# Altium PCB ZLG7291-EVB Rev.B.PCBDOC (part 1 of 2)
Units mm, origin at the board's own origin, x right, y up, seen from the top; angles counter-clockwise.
Board outline 90 x 60 mm, 2 copper layers (Top Layer, Bottom Layer); 77 components, 55 nets, 304 pads, 258 vias.
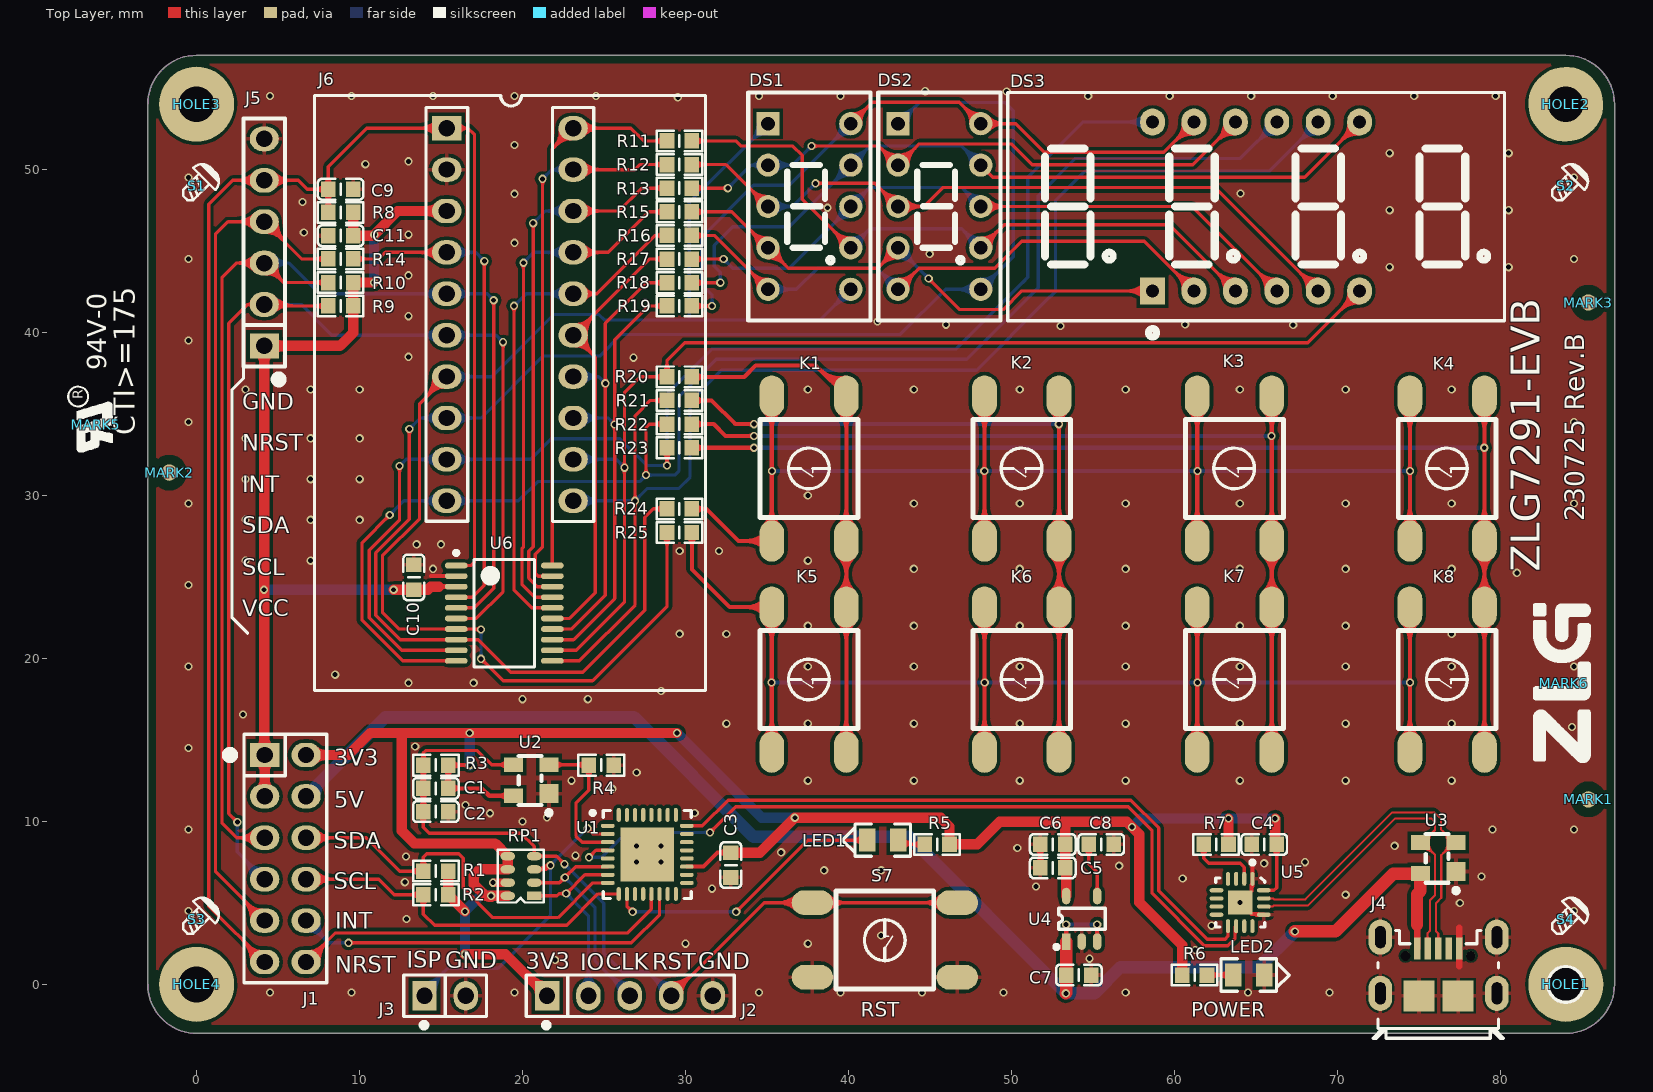
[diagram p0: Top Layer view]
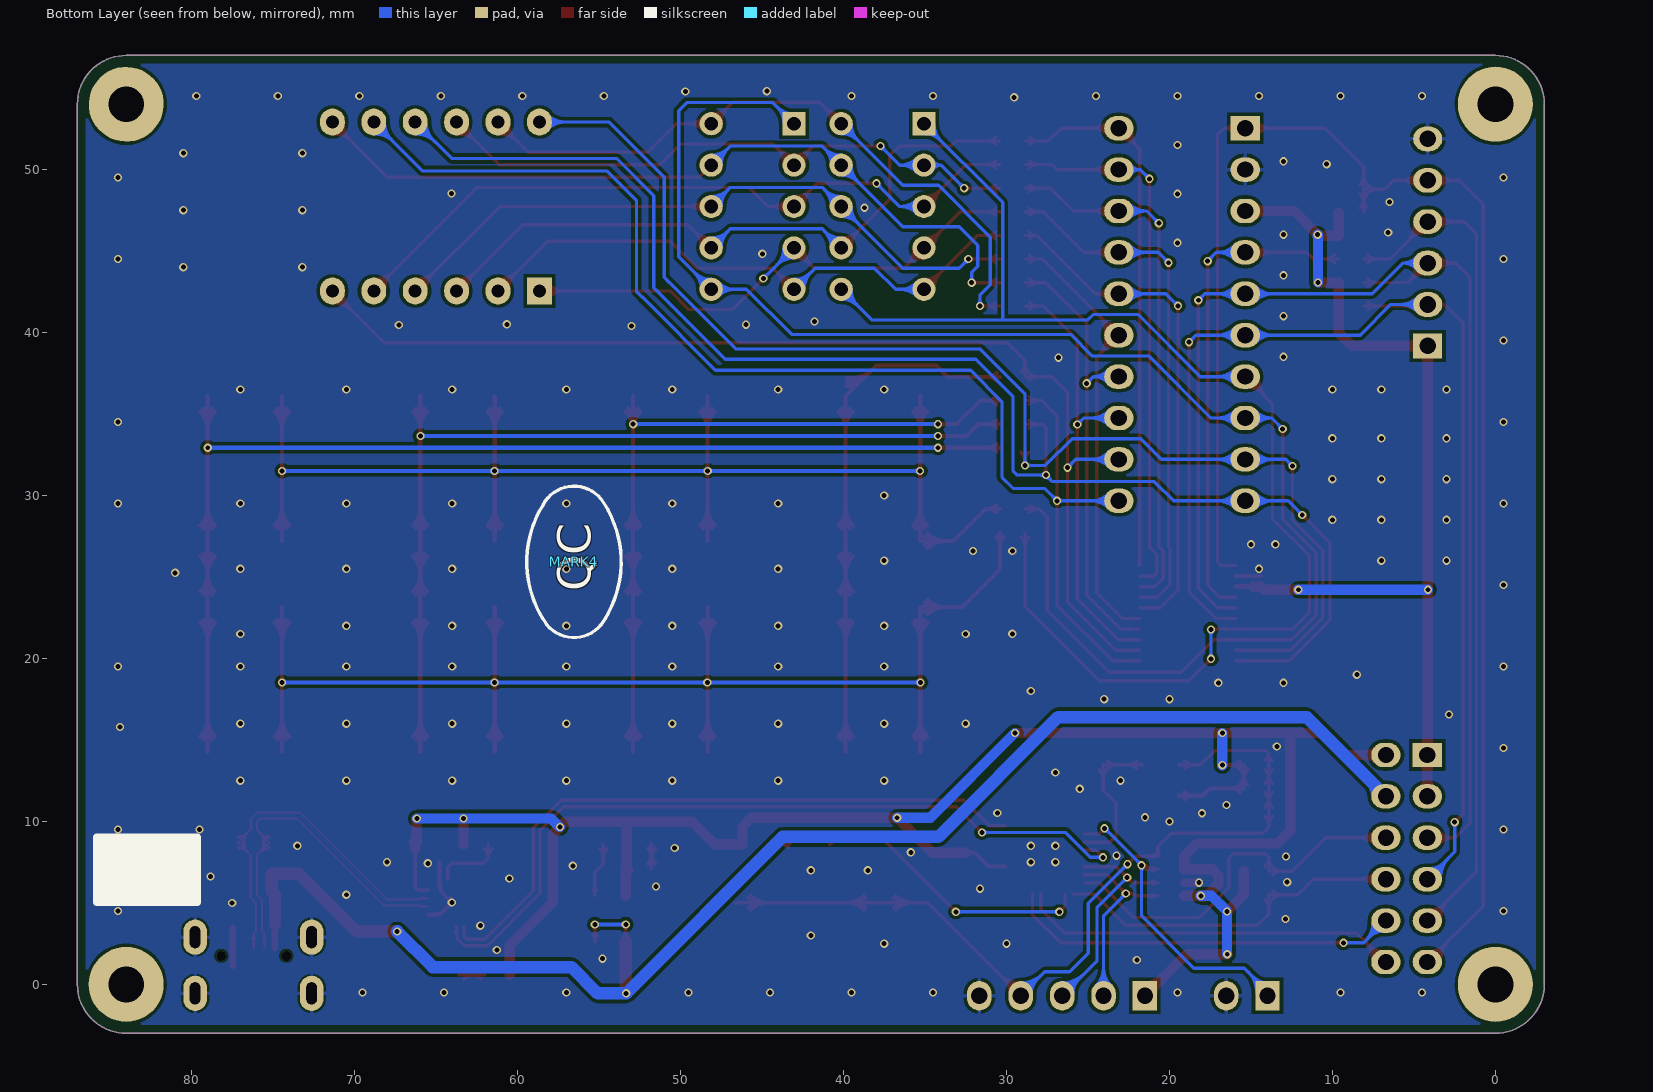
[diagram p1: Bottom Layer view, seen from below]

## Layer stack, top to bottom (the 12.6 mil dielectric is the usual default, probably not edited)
Top Layer: signal copper 0.0356
Dielectric: dielectric 0.32, FR-4, Dk 4.8
Bottom Layer: signal copper 0.0356

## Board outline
-3,0 -3,54 cw(c0,54) 0,57 84,57 cw(c84,54) 87,54 87,0 cw(c84,0) 84,-3 0,-3 cw(c0,0)

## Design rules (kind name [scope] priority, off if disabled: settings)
Clearance Clearance_2 [(OnLayer('Keep-Out Layer'))] p1: gap=0.508
Clearance Clearance_1 [(InComponent('J4'))] p2: gap=0.127
Clearance [All] p3: gap=0.203
ComponentClearance [All] p1 off: gap=0.254 collisioncheckmode=3 verticalgap=0.254 showdistances=FALSE
DiffPairsRouting [All] p1: maxlimit=0.254 minlimit=0.254 mostfreqgap=0.254 maxuncoupledlength=12.7
MinimumSolderMaskSliver [All] p1 off: minsoldermaskwidth=0.254
PolygonConnect PolygonConnect_1 [ISVIA] p1: connectstyle=Direct reliefconductorwidth=0.254 reliefentries=4 polygonreliefangle="90 Angle"
PolygonConnect [All] p2: connectstyle=Relief reliefconductorwidth=0.254 reliefentries=4 polygonreliefangle="90 Angle"
RoutingVias [All] p1: holewidth=0.711 width=1.27 viastyle="Through Hole" minholewidth=0.711 minwidth=1.27 maxholewidth=0.711 maxwidth=1.27
SilkToSilkClearance [All] p1 off: silktosilkclearance=0.254
SilkscreenOverComponentPads [All] p1 off: minsilkscreentomaskgap=0.254
SolderMaskExpansion [All] p1: expansion=0.102
Width [All] p1: maxlimit=2.54 minlimit=0.127 preferedwidth=0.203 minimp=50.000000 maximp=50.000000 favimp=50.000000
23 further rules are at their usual default settings.

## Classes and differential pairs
component class ZLG7291: C9 C10 C11 DS1 DS2 DS3 J5 J6 K1 K2 K3 K4 K5 K6 K7 K8 R8 R9 R10 R11 R12 R13 R14 R15 R16 R17 R18 R19 R20 R21 R22 R23 R24 R25 U6
component class POWER: C4 C5 C6 C7 C8 J4 LED1 LED2 R5 R6 R7 U3 U4 U5
component class LPC824: C1 C2 C3 HOLE1 HOLE2 HOLE3 HOLE4 J1 J2 J3 MARK1 MARK2 MARK3 MARK4 MARK5 MARK6 R1 R2 R3 R4 RP1 S1 S2 S3 S4 S7 U1 U2
differential pair USB: +USB_P -USB_N

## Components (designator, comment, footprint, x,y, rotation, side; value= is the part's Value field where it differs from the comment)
C1 "0.1uF,50V,0603" 0603C 14.675,12.025 r180 top
C2 "0.1uF,50V,0603" 0603C 14.675,10.6 r0 top
C3 "0.1uF,50V,0603" 0603C 32.775,7.325 r270 top
C4 "0.1uF,50V,0603" 0603C 65.5,8.588 r180 top
C5 "10uF,25V,0603" 0603C 52.525,7.15 r180 top
C6 "0.1uF,50V,0603" 0603C 52.525,8.588 r180 top
C7 "10uF,25V,0603" 0603C 54.125,0.575 r0 top
C8 "50V,MURATA,103" 0603C 55.5,8.588 r0 top
C9 "0.1uF,50V,0603" 0603C 8.838,48.785 r0 top
C10 "1uF,50V,0603" 0603C 13.325,24.975 r90 top
C11 "1uF,50V,0603" 0603C 8.838,45.935 r180 top
DS1 "LN3161AS2B,LN" LN3161 37.597,47.725 r0 top
DS2 "LN3161AS2B,LN" LN3161 45.572,47.725 r0 top (schematic designator DS3)
DS3 "LN3461AS2B,LN" LN3461-3000X1400X720 65,47.725 r0 top (schematic designator DS2)
HOLE1 "HOLE - 不上螺丝" HOLE-2.2 84,0 r90 top
HOLE2 "HOLE - 不上螺丝" HOLE-2.2 84,54 r107 top
HOLE3 "HOLE - 不上螺丝" HOLE-2.2 0,54 r330 top
HOLE4 "HOLE - 不上螺丝" HOLE-2.2 0,0 r30 top
J1 "HEADER 6X2" IDC-12-2.54 4.175,14.075 r270 top
J2 "SWD" SIP-5-2.54 21.5,-0.7 r0 top
J3 "ISP" SIP-2-2.54 15.25,-0.7 r0 top
J4 "ST-USB-002B-1,SMT" MICROUSB-ST-USB-002B-1 76.2,1.1 r0 top
J5 "CON6" SIP-6-2.54 4.15,45.525 r90 top
J6 "HEADER 10X2" TEST-TSSOP20 19.225,41.1 r0 top locked
K1 "TS0641-0501B,SMD" KEY-6S 37.575,31.65 r90 top
K2 "TS0641-0501B,SMD" KEY-6S 50.624,31.65 r90 top
K3 "TS0641-0501B,SMD" KEY-6S 63.674,31.65 r90 top
K4 "TS0641-0501B,SMD" KEY-6S 76.723,31.65 r90 top
K5 "TS0641-0501B,SMD" KEY-6S 37.575,18.7 r90 top
K6 "TS0641-0501B,SMD" KEY-6S 50.624,18.7 r90 top
K7 "TS0641-0501B,SMD" KEY-6S 63.674,18.7 r90 top
K8 "TS0641-0501B,SMD" KEY-6S 76.723,18.7 r90 top
LED1 "绿色,0805" LED-0805 42.1,8.85 r180 top
LED2 "红色,0805" LED-0805 64.55,0.575 r0 top
MARK1 "MARKER" MARKER-C-1.0M 85.392,11.351 r0 top
MARK2 "MARKER" MARKER-C-1.0M -1.675,31.4 r0 top
MARK3 "MARKER" MARKER-C-1.0M 85.392,41.831 r0 top
MARK4 "ZY QC" ZY_QC 56.531,25.923 r90 bottom
MARK5 "UR" ZY_UR-3X2 -6.175,34.338 r90 top
MARK6 "ZLGLOGO" ZLG0.5 83.868,18.463 r90 top
R1 "4.7KΩ,±5%,0603" 0603R 14.675,6.95 r0 top
R2 "4.7KΩ,±5%,0603" 0603R 14.675,5.5 r0 top
R3 "10KΩ,±5%,0603" 0603R 14.675,13.45 r0 top
R4 "100KΩ,±5%,0603" 0603R 24.825,13.45 r180 top
R5 "1.5KΩ,±5%,0603" 0603R 45.425,8.588 r180 top
R6 "1.5KΩ,±5%,0603" 0603R 61.225,0.575 r0 top
R7 "4.7KΩ,±5%,0603" 0603R 62.55,8.588 r0 top
R8 "4.7KΩ,±5%,0603" 0603R 8.838,47.36 r0 top
R9 "4.7KΩ,±5%,0603" 0603R 8.838,41.625 r0 top
R10 "4.7KΩ,±5%,0603" 0603R 8.838,43.06 r0 top
R11 "200Ω,±5%,0603" 0603R 29.625,51.75 r0 top
R12 "200Ω,±5%,0603" 0603R 29.625,50.3 r0 top
R13 "200Ω,±5%,0603" 0603R 29.625,48.85 r0 top
R14 "200Ω,±5%,0603" 0603R 8.838,44.51 r0 top
R15 "200Ω,±5%,0603" 0603R 29.625,47.4 r0 top
R16 "200Ω,±5%,0603" 0603R 29.625,45.95 r0 top
R17 "200Ω,±5%,0603" 0603R 29.625,44.5 r0 top
R18 "200Ω,±5%,0603" 0603R 29.625,43.05 r0 top
R19 "200Ω,±5%,0603" 0603R 29.625,41.625 r0 top
R20 "1KΩ,±5%,0603" 0603R 29.625,37.275 r180 top
R21 "1KΩ,±5%,0603" 0603R 29.625,35.825 r180 top
R22 "1KΩ,±5%,0603" 0603R 29.625,34.375 r180 top
R23 "1KΩ,±5%,0603" 0603R 29.625,32.925 r180 top
R24 "1KΩ,±5%,0603" 0603R 29.625,29.175 r180 top
R25 "1KΩ,±5%,0603" 0603R 29.625,27.725 r180 top
RP1 "RTA03-4D103JTP,SMD" 0603RA 19.9,6.65 r180 top
S1 "Value" Screw-Mark2 0,49 r0 top
S2 "Value" Screw-Mark2 84,49 r0 top
S3 "Value" Screw-Mark2 0,4 r0 top
S4 "Value" Screw-Mark2 84,4 r0 top
S7 "DTSM-62R-V-T/R,SMD" KEY-6S 42.225,2.725 r180 top
U1 "LPC824M201JHI33,HVQFN-33" QFN50P500X500X85-33N 27.65,7.975 r0 top
U2 "CAT811STBI-GT3,SOT143(4)" SOT-143 20.525,12.525 r180 top
U3 "PRTR5V0U2X,SOT143/SOT4" sot-143 76.175,7.75 r180 top
U4 "ZL6205A33TS5" SOT-23-5 54.3,4.025 r90 top
U5 "XR21V1410IL16TR-F,QFN-16" QFN50P300X300X80-17AN 64.025,5.025 r270 top
U6 "ZLG7291" TSOP65P640X120-20N 18.875,22.775 r0 top

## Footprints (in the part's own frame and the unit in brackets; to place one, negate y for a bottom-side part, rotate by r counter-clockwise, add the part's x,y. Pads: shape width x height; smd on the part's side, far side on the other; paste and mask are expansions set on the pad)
0603C [mm] "ZLGLIB"
  rect 0.9x0.95 smd: 1(-0.762,0) 2(0.762,0)
  Top Layer pour cut-out: -0.2,0.575 -0.2,-0.575 0.2,-0.575 0.2,0.575
  silkscreen extent -1.4,-0.64 1.4,0.64, body extent -0.79,-0.38 0.81,0.42, height 0.3
0603R [mm] "ZLGLIB"
  rect 0.9x0.95 smd: 1(-0.762,0) 2(0.762,0)
  Top Layer pour cut-out: -0.2,0.575 -0.2,-0.575 0.2,-0.575 0.2,0.575
  silkscreen extent -1.4,-0.64 1.4,0.64, body extent -0.8,-0.4 0.8,0.4, height 0.3
0603RA [mil] "ZLGLIB"
  rect 35x20 smd: 1(-32,48)
  oval 35x20 smd: 2(-32,16) 3(-32,-16) 4(-32,-48) 5(32,-48) 6(32,-16) 7(32,16) 8(32,48)
  Top Layer pour cut-out: -53.5,62 53.5,62 53.5,-62 -53.5,-62
  silkscreen extent -55,-64 56,64, body extent -33,-63 33,63, height 22
HOLE-2.2 [mm]
  round 4.6 hole 2.2: 1(0,0)
IDC-12-2.54 [mm]
  rect 1.5x1.8 hole 1: 1(0,0)
  oval 1.5x1.8 hole 1: 2(0,2.54) 3(2.54,0) 4(2.54,2.54) 5(5.08,0) 6(5.08,2.54) 7(7.62,0) 8(7.62,2.54) 9(10.16,0) 10(10.16,2.54) 11(12.7,0) 12(12.7,2.54)
  silkscreen extent -1.27,-2.38 13.97,3.81, body extent -1.27,-1.27 13.97,3.81, height 7.58
KEY-6S [mil] "ZLGLIB"
  oval 100x60 smd: 1(-175,90) 2(-175,-90) 3(175,-90) 4(175,90)
  silkscreen extent -118,-118 118,118, body extent -201,-122 201,122, height 268
LED-0805 [mm] "170907内距改0.9mm,ZLGLIB"
  rect 1.014x1.4 smd: 1(-0.957,0) 2(0.957,0)
  silkscreen extent -1.7,-0.99 2.49,0.99, body extent -1,-0.64 1,0.64, height 1.1
LN3161 [mil] "ZLGLIB"
  rect 56x56 hole 33: 1(-100,200)
  round 56 hole 33: 2(-100,100) 3(-100,0) 4(-100,-100) 5(-100,-200) 6(100,-200) 7(100,-100) 8(100,0) 9(100,100) 10(100,200)
  silkscreen extent -148,-276 148,276
LN3461-3000X1400X720 [mm] "ZLGLIB"
  rect 1.524x1.651 hole 0.8: 1(-6.35,-5.18)
  oval 1.524x1.651 hole 0.8: 2(-3.81,-5.18) 3(-1.27,-5.18) 4(1.27,-5.18) 5(3.81,-5.18) 6(6.35,-5.18) 7(6.35,5.18) 8(3.81,5.18) 9(1.27,5.18) 10(-1.27,5.18) 11(-3.81,5.18) 12(-6.35,5.18)
  silkscreen extent -15.24,-8 15.24,7
MARKER-C-1.0M [mm]
  round 1 smd paste-1.016 mask+0.5: 0(0,0)
  Top Layer pour cut-out: -1.1,0 -1.016,-0.421 -0.778,-0.778 -0.421,-1.016 0,-1.1 0,-1.1 0.421,-1.016 0.778,-0.778 1.016,-0.421 1.1,0 1.1,0 1.016,0.421 0.778,0.778 0.421,1.016 0,1.1 0,1.1 -0.421,1.016 -0.778,0.778 -1.016,0.421 -1.1,0
MICROUSB-ST-USB-002B-1 [mm] "ZLGLIB"
  oval 1.45x2.15 on Top Paste: 0(-3.575,-1.65) 0(-3.575,1.8) 0(3.575,-1.65) 0(3.575,1.8)
  round 0.55 hole 0.6 unplated: 0(-2.025,0.65) 0(1.975,0.65)
  rect 0.4x1.35 smd: 1(-1.325,1.115) 2(-0.675,1.115) 3(-0.025,1.115) 4(0.625,1.115) 5(1.275,1.115)
  oval 1.45x2.15 hole 0.65 slot 1.35 at 90 deg: 6(-3.575,1.8) 7(3.575,1.8) 8(-3.575,-1.65) 9(3.575,-1.65)
  rect 1.9x1.9 smd: 10(-1.2,-1.8) 11(1.2,-1.8)
  silkscreen extent -4.02,-4.4 3.98,2.2
QFN50P300X300X80-17AN [mm] "ZLGLIB"
  oval 0.85x0.25 smd: 1(-1.45,0.75) 2(-1.45,0.25) 3(-1.45,-0.25) 4(-1.45,-0.75) 9(1.45,-0.75) 10(1.45,-0.25) 11(1.45,0.25) 12(1.45,0.75)
  oval 0.25x0.85 smd: 5(-0.75,-1.45) 6(-0.25,-1.45) 7(0.25,-1.45) 8(0.75,-1.45) 13(0.75,1.45) 14(0.25,1.45) 15(-0.25,1.45) 16(-0.75,1.45)
  rect 1.5x1.5 smd paste-0.3: 17(0,0)
  silkscreen extent -2.57,-1.5 1.5,1.5
QFN50P500X500X85-33N [mm] "QFN, 32-Leads, Body 5.00x5.00mm, Pitch 0.50mm, Thermal Pad 3.60x3.60mm, IPC Medium Density,ZLGLIB"
  oval 0.85x0.25 smd: 1(-2.425,1.75) 2(-2.425,1.25) 3(-2.425,0.75) 4(-2.425,0.25) 5(-2.425,-0.25) 6(-2.425,-0.75) 7(-2.425,-1.25) 8(-2.425,-1.75) 17(2.425,-1.75) 18(2.425,-1.25) 19(2.425,-0.75) 20(2.425,-0.25) 21(2.425,0.25) 22(2.425,0.75) 23(2.425,1.25) 24(2.425,1.75)
  oval 0.25x0.85 smd: 9(-1.75,-2.425) 10(-1.25,-2.425) 11(-0.75,-2.425) 12(-0.25,-2.425) 13(0.25,-2.425) 14(0.75,-2.425) 15(1.25,-2.425) 16(1.75,-2.425) 25(1.75,2.425) 26(1.25,2.425) 27(0.75,2.425) 28(0.25,2.425) 29(-0.25,2.425) 30(-0.75,2.425) 31(-1.25,2.425) 32(-1.75,2.425)
  rect 3.3x3.3 smd: 33(0,0)
  silkscreen extent -3.47,-2.7 2.7,2.7, body extent -2.55,-2.55 2.55,2.55, height 0.85
Screw-Mark2 [mm]
  silkscreen extent -0.83,-0.88 1.37,1.32
SIP-2-2.54 [mm] "ZLGLIB"
  rect 1.5x1.8 hole 1: 1(-1.27,0)
  oval 1.5x1.8 hole 1: 2(1.27,0)
  silkscreen extent -2.54,-1.92 2.54,1.27, body extent -2.54,-1.27 2.54,1.27, height 7.58
SIP-5-2.54 [mm]
  rect 1.5x1.8 hole 1: 1(0,0)
  oval 1.5x1.8 hole 1: 2(2.54,0) 3(5.08,0) 4(7.62,0) 5(10.16,0)
  silkscreen extent -1.27,-1.92 11.48,1.27, body extent -1.27,-1.27 11.43,1.27, height 7.58
SIP-6-2.54 [mil]
  rect 60x70 hole 40: 1(-250,0)
  oval 60x70 hole 40: 2(-150,0) 3(-50,0) 4(50,0) 5(150,0) 6(250,0)
  silkscreen extent -340,-50 299,50, body extent -300,-50 300,50, height 298
SOT-23-5 [mil] "ZLGLIB"
  rect 40x20 smd: 1(-55,37.4)
  oval 40x20 smd: 2(-55,0) 3(-55,-37.4) 4(55,-37.4) 5(55,37.4)
  silkscreen extent -73,-57 26,66, body extent -55,-57 55,57, height 43
SOT-143 [mil] "SOT-143B,ZLGLIB"
  rect 46x46 smd: 1(-43,32.5)
  rect 46x36 smd: 2(-43,-37.5) 3(43,-37.5) 4(43,37.5)
  silkscreen extent -49,-58 30,84
sot-143 [mil] "SOT-143B,ZLGLIB"
  rect 46x46 smd: 1(-43,32.5)
  rect 46x36 smd: 2(-43,-37.5) 3(43,-37.5) 4(43,37.5)
  silkscreen extent -49,-58 30,84
TEST-TSSOP20 [mm]
  rect 1.8x1.5 hole 1: 1(-3.875,11.43)
  oval 1.8x1.5 hole 1: 2(-3.875,8.89) 3(-3.875,6.35) 4(-3.875,3.81) 5(-3.875,1.27) 6(-3.875,-1.27) 7(-3.875,-3.81) 8(-3.875,-6.35) 9(-3.875,-8.89) 10(-3.875,-11.43) 11(3.875,-11.43) 12(3.875,-8.89) 13(3.875,-6.35) 14(3.875,-3.81) 15(3.875,-1.27) 16(3.875,1.27) 17(3.875,3.81) 18(3.875,6.35) 19(3.875,8.89) 20(3.875,11.43)
  silkscreen extent -12,-23.07 12,13.43, body extent -5.14,-12.7 5.15,12.7, height 7.58
TSOP65P640X120-20N [mm] "TSOP, 20-Leads, Body 6.50x4.40mm, Pitch 0.65mm, IPC Medium Density,ZLGLIB"
  oval 1.4x0.35 smd: 1(-2.95,2.925) 2(-2.95,2.275) 3(-2.95,1.625) 4(-2.95,0.975) 5(-2.95,0.325) 6(-2.95,-0.325) 7(-2.95,-0.975) 8(-2.95,-1.625) 9(-2.95,-2.275) 10(-2.95,-2.925) 11(2.95,-2.925) 12(2.95,-2.275) 13(2.95,-1.625) 14(2.95,-0.975) 15(2.95,-0.325) 16(2.95,0.325) 17(2.95,0.975) 18(2.95,1.625) 19(2.95,2.275) 20(2.95,2.925)
  silkscreen extent -3.07,-3.3 1.85,3.82, body extent -3.2,-3.3 3.2,3.3, height 1.2
ZLG0.5 [mm]
  silkscreen extent -4.87,-1.65 4.93,1.83
ZY_QC [mm]
  silkscreen extent -4.64,-2.89 4.64,2.89
ZY_UR-3X2 [mm]
  silkscreen extent -1.7,-1.02 2.34,1.7

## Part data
C1 C2 C3 C4 C6 C9: library part 02.01.00015, "C1608X7R1H104KT000N,0603,TDK,0.1uF,X7R,±10%,50V,"
C5 C7: library part 02.01.00543, "GRM188R61E106MA73D,0603,MURATA,10uF,X5R,±20%,25V"
C8: library part 02.01.00364, "GCM188R71H103KA15D,103,±10%,50V,X7R,0603,MURATA,"
C10 C11: library part 02.01.00497, "C1608X5R1H105K080AB,0603,TDK,1uF,X5R,±10%,50V"
DS1 DS2: "LN3161AS2B,LN,A/1,14*7.5*8.5mm,"
DS3: library part 16.03.00006, "LN3461AS2B,LN,A/1,30*14*7.3mm,"
J2: library part "Header 5H", "Header, 5-Pin, Right Angle"
J3: library part "Header 2H", "Header, 2-Pin, Right Angle"
J4: library part 20.02.00033, "ST-USB-002B-1,SMT,SUNGTECH,MicroUSB-A"
J5: "Connector"
K1 K2 K3 K4 K5 K6 K7 K8: library part 17.01.00005, "TS0641-0501B,SMD,DAILYLON,黑色,卷带装,6*6*5.0mm,"
LED1: library part 04.04.00006, "0805QBGC-G,SMD,BRIGHT,翠绿色,"
LED2: library part 04.04.00010, "0805QRC,SMD,BRIGHT,红色,"
MARK6: "ZLGLIB"
R1 R2 R7 R8 R9 R10: library part 01.01.00005, "RTT03472JTP,0603,RALEC,4.7KΩ,±5%,1/10W,"
R3: library part 01.01.00002, "RTT03103JTP,0603,RALEC,10KΩ,±5%,1/10W,"
R4: library part 01.01.00031, "RTT03104JTP,0603,RALEC,100KΩ,±5%,1/10W,"
R5 R6: library part 01.01.00039, "RTT03152JTP,0603,RALEC,1.5KΩ,±5%,1/10W,"
R11 R12 R13 R14 R15 R16 R17 R18 R19: library part 01.01.00202, "RTT03201JTP,0603,RALEC,200Ω,±5%,1/10W,"
R20 R21 R22 R23 R24 R25: library part 01.01.00012, "RTT03102JTP,0603,RALEC,1KΩ,±5%,1/10W,"
RP1: library part 01.02.00003, "RTA03-4D103JTP,SMD,RALEC,10KΩ*4,"
S1 S2 S3 S4: library part Screw-Mark
S7: library part 17.01.00031, "DTSM-62R-V-T/R,SMD,DIP,红色,6.2*6.2*5mm,圆达"
U1: library part 08.01.02201, "LPC824M201JHI33,HVQFN-33,NXP,"
U2: library part 08.09.01426, "CAT811STBI-GT3,SOT143(4),ON,"
U3: library part 09.04.00190, "PRTR5V0U2X,SOT143/SOT4,NEXPERIA,"
U4: library part 89.12.00013
U5: library part 08.08.00611, "XR21V1410IL16TR-F,QFN-16,EXAR,"

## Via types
v1: diameter 0.508, hole 0.305, Top Layer to Bottom Layer, tented both sides, 258 vias

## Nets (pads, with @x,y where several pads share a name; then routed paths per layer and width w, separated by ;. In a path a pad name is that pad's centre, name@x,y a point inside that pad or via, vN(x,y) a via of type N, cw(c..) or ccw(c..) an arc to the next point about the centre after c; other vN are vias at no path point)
3.3V: C1.1 C3.1 C4.1 C5.1 C6.1 J1.2 J2.1 R1.2 R2.2 R3.2 R5.1 R6.1 R7.2 RP1.5 RP1.6 RP1.8 U1.19 U2.4 U4.5 U5.16 | length 149.5
  Top Layer w0.203: U5.16@65.475,5.775 66.1,5.775 66.262,5.937 C4.1@66.262,8.588 ; C4.1@66.016,8.317 cw(c65.421,7.722) 66.262,7.722 cw(c67.103,7.722) C4.1@66.508,8.317
  Top Layer w0.254: C1.1@15.209,12.278 ccw(c14.657,12.83) 15.437,12.83 ccw(c16.217,12.83) C1.1@15.665,12.278 ; R3.2@15.209,13.197 cw(c14.657,12.645) 15.437,12.645 cw(c16.217,12.645) R3.2@15.665,13.197 ; C1.1@15.665,11.797 cw(c16.217,11.245) 16.217,12.025 cw(c16.217,12.805) C1.1@15.665,12.253 ; R3.2@15.665,13.222 cw(c16.217,12.67) 16.217,13.45 cw(c16.217,14.23) R3.2@15.665,13.678 ; v1@16.66,13.36 ccw(c16.443,13.143) 16.443,13.45 ccw(c16.443,13.757) v1@16.66,13.54 ; v1(16.75,13.45) R3.2@15.437,13.45 C1.1@15.437,12.025 17.5,12.025 17.953,11.573 U2.4@19.433,11.573 ; U2.4@19.072,11.339 ccw(c18.509,10.775) 18.509,11.573 ccw(c18.509,12.37) U2.4@19.072,11.806 ; U1.19@30.075,7.225 31.1,7.225 31.962,8.087 C3.1@32.775,8.087 ; C3.1@32.522,7.859 ccw(c31.97,7.307) 31.97,8.087 ccw(c31.97,8.867) C3.1@32.522,8.315
  Top Layer w0.635: J1.2@6.715,14.075 9.3,14.075 10.65,15.425 12.576,15.425 ; J1.2@7.171,13.769 cw(c7.909,13.031) 7.909,14.075 cw(c7.909,15.119) J1.2@7.171,14.381 ; R1.2@15.437,6.95 R2.2@15.437,5.5 v1(16.462,4.475) ; v1(16.45,1.85) 18.95,1.85 J2.1@21.5,-0.7 ; 17.589,5.566 ccw(c18.069,6.047) v1@18.069,5.367 ; RP1.8@19.087,5.431 v1(18.069,5.431) 17.724,5.431 17,6.155 17,6.675 17.381,7.056 RP1.6@19.087,7.056 RP1.5@19.087,7.869 18.309,8.647 13.353,8.647 12.576,9.424 12.576,15.425 ; 20.506,0.294 ccw(c21.5,1.289) J2.1@21.5,-0.118 ; J2.1@20.868,-0.068 cw(c20.385,-0.55) J2.1@21.068,-0.55 ; v1(29.475,15.425) 12.576,15.425 ; C3.1@32.775,8.087 34.562,8.087 v1(36.7,10.225) 45.65,10.225 46.187,9.688 R5.1@46.187,8.588 47.888,8.588 49.275,9.975 53.275,9.975 ; C5.1@53.193,7.031 cw(c52.815,6.653) 53.35,6.653 ; U4.5@53.35,5.422 53.35,7.087 C5.1@53.287,7.15 C6.1@53.287,8.588 53.287,9.963 53.275,9.975 ; R6.1@60.463,0.575 60.463,2.412 57.825,5.05 57.825,9.225 v1(57.394,9.656) 57.075,9.975 53.275,9.975 ; R7.2@63.312,8.588 v1(63.312,10.175) ; 66.175,9.143 ccw(c66.792,9.143) C4.1@66.356,8.707 ; v1(66.175,10.175) 66.175,8.675 C4.1@66.262,8.588
  Bottom Layer w0.635: v1@16.462,1.862 v1(16.462,4.475) 17.418,5.431 v1(18.069,5.431) ; v1(16.75,13.45) v1(16.75,15.425) ; v1(29.475,15.425) 34.675,10.225 v1(36.7,10.225) ; v1(57.394,9.656) 57.914,10.175 v1(63.312,10.175) v1(66.175,10.175)
5V: C7.1 J1.4 J4.1 U3.4 U4.1 U4.3 | length 96.1
  Top Layer w0.254: U4.1@53.26,2.972 ccw(c53.043,3.189) 53.35,3.189 ccw(c53.657,3.189) U4.1@53.44,2.972 ; v1@53.26,3.585 cw(c53.043,3.368) 53.35,3.368 cw(c53.657,3.368) v1@53.44,3.585 ; U4.1@53.35,2.628 v1@53.35,3.7 ; U4.3@55.16,2.972 ccw(c54.943,3.189) 55.25,3.189 ccw(c55.557,3.189) U4.3@55.34,2.972 ; v1@55.16,3.585 cw(c54.943,3.368) 55.25,3.368 cw(c55.557,3.368) v1@55.34,3.585 ; U4.3@55.25,2.628 v1(55.25,3.675)
  Top Layer w0.4: J4.1@74.875,2.215 74.875,3.65
  Top Layer w0.762: v1(53.325,-0.55) 53.363,-0.512 C7.1@53.363,0.575 ; U4.1@53.35,2.628 53.35,0.663 C7.1@53.363,0.65 ; v1(67.375,3.25) 69.875,3.25 73.422,6.797 U3.4@75.083,6.797 75.083,5.733 74.875,5.525 74.875,3.65
  Bottom Layer w0.254: v1(53.35,3.675) v1(55.25,3.675) ; v1@53.44,3.585 cw(c53.657,3.368) 53.657,3.675 cw(c53.657,3.982) v1@53.44,3.765 ; v1@55.16,3.585 ccw(c54.943,3.368) 54.943,3.675 ccw(c54.943,3.982) v1@55.16,3.765
  Bottom Layer w0.762: J1.4@6.715,11.535 11.58,16.4 26.825,16.4 34.175,9.05 43.725,9.05 v1(53.325,-0.55) 55.075,-0.55 56.689,1.064 65.189,1.064 v1(67.375,3.25) ; J1.4@7.234,11.535 cw(c8.487,11.535) 7.601,12.421
A: DS1.10 DS2.10 DS3.11 R19.2 | length 63.5
  Top Layer w0.203: R19.2@30.387,41.625 v1(31.623,41.625) ; R19.2@30.633,41.379 cw(c31.228,40.784) 31.228,41.625 cw(c31.228,42.466) R19.2@30.633,41.871 ; v1@31.515,41.517 ccw(c31.255,41.257) 31.255,41.625 ccw(c31.255,41.993) v1@31.515,41.733 ; DS1.10@40.137,52.805 41.457,54.125 46.792,54.125 DS2.10@48.112,52.805 50.265,52.805 52.016,51.054 59.339,51.054 DS3.11@61.19,52.905 ; DS1.10@40.137,53.211 ccw(c40.137,54.193) 40.831,53.499 ccw(c41.525,52.805) DS1.10@40.543,52.805 ; DS1.10@40.137,53.415 ccw(c40.137,54.886) 41.178,53.846 ccw(c42.218,52.805) DS1.10@40.747,52.805 ; DS2.10@47.502,52.805 ccw(c46.031,52.805) 47.071,53.846 ccw(c48.112,54.886) DS2.10@48.112,53.415 ; DS2.10@47.706,52.805 ccw(c46.724,52.805) 47.418,53.499 ccw(c48.112,54.193) DS2.10@48.112,53.211 ; DS2.10@48.399,52.518 cw(c49.093,51.824) 49.093,52.805 cw(c49.093,53.786) DS2.10@48.399,53.092 ; DS2.10@48.543,52.374 cw(c49.584,51.333) 49.584,52.805 cw(c49.584,54.277) DS2.10@48.543,53.236 ; 59.954,51.669 cw(c61.19,50.433) DS3.11@61.19,52.181 ; 60.108,51.823 ccw(c59.089,52.841) DS3.11@60.53,52.841 ; 60.301,52.016 cw(c61.19,51.127) DS3.11@61.19,52.384 ; 60.454,52.169 ccw(c59.782,52.841) DS3.11@60.733,52.841
  Bottom Layer w0.203: v1@31.515,41.733 ccw(c31.255,41.993) 31.623,41.993 ccw(c31.991,41.993) v1@31.731,41.733 ; v1(31.623,41.625) 31.623,42.291 30.988,42.926 30.988,45.847 34.163,49.022 36.354,49.022 DS1.10@40.137,52.805 ; DS1.10@39.527,52.805 cw(c38.056,52.805) 39.096,51.764 cw(c40.137,50.724) DS1.10@40.137,52.195 ; DS1.10@39.731,52.805 cw(c38.749,52.805) 39.443,52.111 cw(c40.137,51.417) DS1.10@40.137,52.399
B: DS1.9 DS2.9 DS3.7 R18.2 | length 66.8
  Top Layer w0.203: R18.2@30.387,43.05 v1(32.131,43.05) ; R18.2@30.633,42.804 cw(c31.228,42.209) 31.228,43.05 cw(c31.228,43.891) R18.2@30.633,43.296 ; v1@32.023,42.942 ccw(c31.763,42.682) 31.763,43.05 ccw(c31.763,43.418) v1@32.023,43.158 ; DS2.9@48.112,50.265 48.847,49.53 67.975,49.53 DS3.7@71.35,52.905 ; 70.114,51.669 cw(c71.35,50.433) DS3.7@71.35,52.181 ; 70.268,51.823 ccw(c69.249,52.841) DS3.7@70.69,52.841 ; 70.461,52.016 cw(c71.35,51.127) DS3.7@71.35,52.384 ; 70.614,52.169 ccw(c69.942,52.841) DS3.7@70.893,52.841
  Bottom Layer w0.203: v1@32.023,43.158 ccw(c31.763,43.418) 32.131,43.418 ccw(c32.499,43.418) v1@32.239,43.158 ; v1(32.131,43.05) 32.131,43.688 31.75,44.069 31.75,45.339 32.893,46.482 36.354,46.482 DS1.9@40.137,50.265 41.307,51.435 46.942,51.435 DS2.9@48.112,50.265 ; DS1.9@39.527,50.265 cw(c38.056,50.265) 39.096,49.224 cw(c40.137,48.184) DS1.9@40.137,49.655 ; DS1.9@39.731,50.265 cw(c38.749,50.265) 39.443,49.571 cw(c40.137,48.877) DS1.9@40.137,49.859 ; DS1.9@40.137,50.671 ccw(c40.137,51.653) 40.831,50.959 ccw(c41.525,50.265) DS1.9@40.543,50.265 ; DS1.9@40.137,50.875 ccw(c40.137,52.346) 41.178,51.306 ccw(c42.218,50.265) DS1.9@40.747,50.265 ; DS2.9@47.502,50.265 ccw(c46.031,50.265) 47.071,51.306 ccw(c48.112,52.346) DS2.9@48.112,50.875 ; DS2.9@47.706,50.265 ccw(c46.724,50.265) 47.418,50.959 ccw(c48.112,51.653) DS2.9@48.112,50.671
C: DS1.8 DS2.8 DS3.4 R17.2 | length 62.9
  Top Layer w0.203: R17.2@30.387,44.5 v1(32.335,44.5) ; R17.2@30.633,44.254 cw(c31.228,43.659) 31.228,44.5 cw(c31.228,45.341) R17.2@30.633,44.746 ; v1@32.227,44.392 ccw(c31.967,44.132) 31.967,44.5 ccw(c31.967,44.868) v1@32.227,44.608 ; DS2.8@48.112,47.725 61.09,47.725 DS3.4@66.27,42.545 ; DS2.8@48.399,47.438 cw(c49.093,46.744) 49.093,47.725 cw(c49.093,48.706) DS2.8@48.399,48.012 ; DS2.8@48.543,47.294 cw(c49.584,46.253) 49.584,47.725 cw(c49.584,49.197) DS2.8@48.543,48.156 ; 65.034,43.781 ccw(c66.27,45.017) DS3.4@66.27,43.269 ; 65.188,43.627 cw(c64.169,42.608) DS3.4@65.61,42.608 ; 65.381,43.434 ccw(c66.27,44.323) DS3.4@66.27,43.066 ; 65.534,43.281 cw(c64.862,42.608) DS3.4@65.813,42.608
  Bottom Layer w0.203: v1@32.335,44.348 cw(c32.335,43.98) 32.595,44.24 cw(c32.855,44.5) v1@32.487,44.5 ; v1(32.335,44.5) 32.893,43.942 36.354,43.942 DS1.8@40.137,47.725 41.307,48.895 46.942,48.895 DS2.8@48.112,47.725 ; DS1.8@39.527,47.725 cw(c38.056,47.725) 39.096,46.684 cw(c40.137,45.644) DS1.8@40.137,47.115 ; DS1.8@39.731,47.725 cw(c38.749,47.725) 39.443,47.031 cw(c40.137,46.337) DS1.8@40.137,47.319 ; DS1.8@40.137,48.131 ccw(c40.137,49.113) 40.831,48.419 ccw(c41.525,47.725) DS1.8@40.543,47.725 ; DS1.8@40.137,48.335 ccw(c40.137,49.806) 41.178,48.766 ccw(c42.218,47.725) DS1.8@40.747,47.725 ; DS2.8@47.502,47.725 ccw(c46.031,47.725) 47.071,48.766 ccw(c48.112,49.806) DS2.8@48.112,48.335 ; DS2.8@47.706,47.725 ccw(c46.724,47.725) 47.418,48.419 ccw(c48.112,49.113) DS2.8@48.112,48.131
COM0: DS3.6 J6.12 R20.2 U6.12 | length 83.2
  Top Layer w0.203: U6.12@21.825,20.5 23.3,20.5 26.25,23.45 v1(26.25,31.7) 26.25,36.3 27.225,37.275 R20.2@28.863,37.275 28.863,38.288 29.95,39.375 67.378,39.375 68.18,39.375 DS3.6@71.35,42.545 ; U6.12@22.402,20.448 cw(c22.527,20.323) 22.527,20.5 cw(c22.527,20.677) U6.12@22.402,20.552 ; v1@26.142,31.592 cw(c25.882,31.332) 26.25,31.332 cw(c26.618,31.332) v1@26.358,31.592 ; v1@26.142,31.808 ccw(c25.882,32.068) 26.25,32.068 ccw(c26.618,32.068) v1@26.358,31.808 ; R20.2@28.617,37.029 ccw(c28.022,36.434) 28.022,37.275 ccw(c28.022,38.116) R20.2@28.617,37.521 ; R20.2@28.617,37.546 ccw(c28.022,38.141) 28.863,38.141 ccw(c29.704,38.141) R20.2@29.109,37.546 ; 70.114,41.309 cw(c71.35,40.073) DS3.6@71.35,41.821 ; 70.268,41.463 ccw(c69.249,42.481) DS3.6@70.69,42.481 ; 70.461,41.656 cw(c71.35,40.767) DS3.6@71.35,42.024 ; 70.614,41.809 ccw(c69.942,42.481) DS3.6@70.893,42.481
  Bottom Layer w0.203: J6.12@23.1,32.21 25.74,32.21 v1(26.25,31.7) ; J6.12@23.565,31.895 cw(c24.325,31.135) 24.325,32.21 cw(c24.325,33.285) J6.12@23.565,32.525 ; J6.12@23.708,31.752 cw(c24.815,30.645) 24.815,32.21 cw(c24.815,33.775) J6.12@23.708,32.668 ; v1@26.098,31.7 ccw(c25.73,31.7) 25.99,31.96 ccw(c26.25,32.22) v1@26.25,31.852
COM1: DS3.8 J6.11 R21.2 U6.11 | length 94.7
  Top Layer w0.203: U6.11@21.825,19.85 23.475,19.85 26.9,23.275 26.9,34.9 27.825,35.825 R21.2@28.863,35.825 ; U6.11@22.402,19.798 cw(c22.527,19.673) 22.527,19.85 cw(c22.527,20.027) U6.11@22.402,19.902 ; v1@26.787,29.562 cw(c26.515,29.29) 26.9,29.29 ; v1@26.787,29.778 ccw(c26.515,30.05) 26.9,30.05 ; 26.9,29.314 cw(c27.251,29.314) v1@27.003,29.562 ; 26.9,30.026 ccw(c27.251,30.026) v1@27.003,29.778 ; R21.2@28.617,35.579 ccw(c28.022,34.984) 28.022,35.825 ccw(c28.022,36.666) R21.2@28.617,36.071
  Bottom Layer w0.203: J6.11@23.1,29.67 v1(26.895,29.67) 27.65,30.425 29.575,30.425 30.275,31.125 30.275,35.75 32.2,37.675 47.85,37.675 52.077,41.902 ; J6.11@23.565,29.355 cw(c24.325,28.595) 24.325,29.67 cw(c24.325,30.745) J6.11@23.565,29.985 ; J6.11@23.708,29.212 cw(c24.815,28.105) 24.815,29.67 cw(c24.815,31.235) J6.11@23.708,30.128 ; v1@26.787,29.562 ccw(c26.527,29.302) 26.527,29.67 ccw(c26.527,30.038) v1@26.787,29.778 ; v1@26.895,29.822 ccw(c26.895,30.19) 27.155,29.93 ccw(c27.415,29.67) v1@27.047,29.67 ; 52.5,42.325 52.077,41.902 ; 67.574,51.669 cw(c68.81,50.433) DS3.8@68.81,52.181 ; 67.728,51.823 ccw(c66.709,52.841) DS3.8@68.15,52.841 ; 67.921,52.016 cw(c68.81,51.127) DS3.8@68.81,52.384 ; 68.074,52.169 ccw(c67.402,52.841) DS3.8@68.353,52.841 ; DS3.8@68.81,52.905 65.805,49.9 54.5,49.9 52.7,48.1 52.7,43.252 52.7,42.525 52.077,41.902
COM2: DS3.9 J6.10 R22.2 U6.10 | length 106
  Top Layer w0.203: v1@11.698,28.8 cw(c11.33,28.8) 11.59,28.54 cw(c11.85,28.28) v1@11.85,28.648 ; v1(11.85,28.8) 10.15,27.1 10.15,22.351 12.651,19.85 U6.10@15.925,19.85 ; U6.10@15.348,19.798 ccw(c15.223,19.673) 15.223,19.85 ccw(c15.223,20.027) U6.10@15.348,19.902 ; v1@27.467,31.358 ccw(c27.207,31.618) 27.575,31.618 ccw(c27.943,31.618) v1@27.683,31.358 ; v1(27.575,31.25) 27.575,34.175 27.775,34.375 R22.2@28.863,34.375 ; R22.2@28.617,34.129 ccw(c28.022,33.534) 28.022,34.375 ccw(c28.022,35.216) R22.2@28.617,34.621
  Bottom Layer w0.203: v1(11.85,28.8) 12.72,29.67 J6.10@15.35,29.67 19.745,29.67 20.925,30.85 27.175,30.85 v1(27.575,31.25) 29.345,31.25 29.591,31.496 29.591,36.068 31.877,38.354 47.244,38.354 51.197,42.307 ; v1@11.85,28.952 ccw(c11.85,29.32) 12.11,29.06 ccw(c12.37,28.8) v1@12.002,28.8 ; J6.10@14.742,29.212 ccw(c13.635,28.105) 13.635,29.67 ccw(c13.635,31.235) J6.10@14.742,30.128 ; J6.10@14.885,29.355 ccw(c14.125,28.595) 14.125,29.67 ccw(c14.125,30.745) J6.10@14.885,29.985 ; J6.10@15.815,29.355 cw(c16.575,28.595) 16.575,29.67 cw(c16.575,30.745) J6.10@15.815,29.985 ; J6.10@15.958,29.212 cw(c17.065,28.105) 17.065,29.67 cw(c17.065,31.235) J6.10@15.958,30.128 ; v1@27.423,31.25 cw(c27.055,31.25) 27.315,30.99 cw(c27.575,30.73) v1@27.575,31.098 ; v1@27.683,31.142 cw(c27.943,30.882) 27.943,31.25 cw(c27.943,31.618) v1@27.683,31.358 ; 51.435,42.545 51.197,42.307 ; 65.034,51.669 cw(c66.27,50.433) DS3.9@66.27,52.181 ; 65.188,51.823 ccw(c64.169,52.841) DS3.9@65.61,52.841 ; 65.381,52.016 cw(c66.27,51.127) DS3.9@66.27,52.384 ; 65.534,52.169 ccw(c64.862,52.841) DS3.9@65.813,52.841 ; DS3.9@66.27,52.905 64.038,50.673 53.921,50.673 51.635,48.387 51.635,43.627 51.635,42.745 51.197,42.307
COM3: DS3.12 J6.9 R23.2 U6.9 | length 97.3
  Top Layer w0.203: v1@12.342,31.692 cw(c12.082,31.432) 12.45,31.432 cw(c12.818,31.432) v1@12.558,31.692 ; v1(12.45,31.8) 12.45,28.499 10.587,26.637 10.587,22.488 12.576,20.5 U6.9@15.925,20.5 ; U6.9@15.348,20.448 ccw(c15.223,20.323) 15.223,20.5 ccw(c15.223,20.677) U6.9@15.348,20.552 ; R23.2@28.617,32.654 cw(c28.022,32.059) 28.863,32.059 cw(c29.704,32.059) R23.2@29.109,32.654 ; v1@28.755,31.946 ccw(c28.495,32.206) 28.863,32.206 ccw(c29.231,32.206) v1@28.971,31.946 ; v1(28.863,31.838) R23.2@28.863,32.925
  Bottom Layer w0.203: v1(12.45,31.8) 12.86,32.21 J6.9@15.35,32.21 20.49,32.21 21.755,33.475 25.975,33.475 27.612,31.838 v1(28.863,31.838) 28.863,36.229 31.623,38.989 46.609,38.989 50.5,42.88 ; v1@12.45,31.952 ccw(c12.45,32.32) 12.71,32.06 ccw(c12.97,31.8) v1@12.602,31.8 ; J6.9@14.742,31.752 ccw(c13.635,30.645) 13.635,32.21 ccw(c13.635,33.775) J6.9@14.742,32.668 ; J6.9@14.885,31.895 ccw(c14.125,31.135) 14.125,32.21 ccw(c14.125,33.285) J6.9@14.885,32.525 ; J6.9@15.815,31.895 cw(c16.575,31.135) 16.575,32.21 cw(c16.575,33.285) J6.9@15.815,32.525 ; J6.9@15.958,31.752 cw(c17.065,30.645) 17.065,32.21 cw(c17.065,33.775) J6.9@15.958,32.668 ; v1@28.755,31.73 ccw(c28.495,31.47) 28.495,31.838 ccw(c28.495,32.206) 28.755,31.946 ccw(c28.495,32.206) 28.863,32.206 ccw(c29.231,32.206) v1@28.971,31.946 ; 50.8,43.18 50.5,42.88 ; DS3.12@58.183,52.438 ccw(c57.056,51.311) 57.056,52.905 ccw(c57.056,54.499) DS3.12@58.183,53.372 ; DS3.12@58.327,52.582 ccw(c57.546,51.801) 57.546,52.905 ccw(c57.546,54.009) DS3.12@58.327,53.228 ; DS3.12@58.65,52.905 54.375,52.905 51,49.53 51,44.177 51,43.38 50.5,42.88
COM8: DS2.1 DS2.6 J6.8 R24.2 U6.8 | length 119.8
  Top Layer w0.203: v1@12.942,33.967 cw(c12.682,33.707) 13.05,33.707 cw(c13.418,33.707) v1@13.158,33.967 ; v1(13.05,34.075) 13.05,28.525 10.994,26.468 10.994,22.657 12.5,21.15 U6.8@15.925,21.15 17.275,21.15 19.275,19.15 23.697,19.15 27.5,22.953 27.5,28.65 28.025,29.175 ; U6.8@15.348,21.098 ccw(c15.223,20.973) 15.223,21.15 ccw(c15.223,21.327) U6.8@15.348,21.202 ; U6.8@16.502,21.098 cw(c16.627,20.973) 16.627,21.15 cw(c16.627,21.327) U6.8@16.502,21.202 ; R24.2@28.616,28.929 ccw(c28.025,28.342) 28.025,29.175 ; R24.2@28.616,29.421 cw(c28.025,30.008) 28.025,29.175 ; R24.2@28.863,29.175 28.025,29.175
  Bottom Layer w0.203: v1(13.05,34.075) 13.725,34.75 ; v1@13.05,34.227 ccw(c13.05,34.595) 13.31,34.335 ccw(c13.57,34.075) v1@13.202,34.075 ; J6.8@14.722,34.312 ccw(c13.725,33.397) 13.725,34.75 ; J6.8@14.722,35.188 cw(c13.725,36.103) 13.725,34.75 ; J6.8@14.872,34.449 ccw(c14.187,33.821) 14.187,34.75 ccw(c14.187,35.679) J6.8@14.872,35.051 ; J6.8@15.815,34.435 cw(c16.575,33.675) 16.575,34.75 cw(c16.575,35.825) J6.8@15.815,35.065 ; J6.8@15.958,34.292 cw(c17.065,33.185) 17.065,34.75 cw(c17.065,36.315) J6.8@15.958,35.208 ; DS2.1@43.032,52.805 44.329,54.102 49.603,54.102 50.111,53.594 50.111,44.644 DS2.6@48.112,42.645 45.947,42.645 43.18,39.878 26.053,39.878 24.725,38.55 21.25,38.55 17.45,34.75 J6.8@15.35,34.75 13.725,34.75 ; DS2.1@43.032,53.211 ccw(c43.032,54.193) 43.726,53.499 ccw(c44.42,52.805) DS2.1@43.438,52.805 ; DS2.1@43.032,53.415 ccw(c43.032,54.886) 44.073,53.846 ccw(c45.113,52.805) DS2.1@43.642,52.805 ; DS2.6@47.681,42.214 ccw(c46.64,41.173) 46.64,42.645 ccw(c46.64,44.117) DS2.6@47.681,43.076 ; DS2.6@47.825,42.358 ccw(c47.131,41.664) 47.131,42.645 ccw(c47.131,43.626) DS2.6@47.825,42.932 ; DS2.6@48.112,43.051 ccw(c48.112,44.033) 48.806,43.339 ccw(c49.5,42.645) DS2.6@48.518,42.645 ; DS2.6@48.112,43.255 ccw(c48.112,44.726) 49.153,43.686 ccw(c50.193,42.645) DS2.6@48.722,42.645
COM9: DS1.1 DS1.6 J6.7 R25.2 U6.7 | length 105
  Top Layer w0.203: 13.987,35.927 ccw(c12.624,37.29) J6.7@14.552,37.29 ; 14.334,36.274 ccw(c13.318,37.29) J6.7@14.755,37.29 ; 14.349,36.289 cw(c15.2,35.438) J6.7@15.2,36.642 ; 14.681,36.621 ccw(c14.012,37.29) J6.7@14.958,37.29 ; 14.696,36.636 cw(c15.2,36.132) J6.7@15.2,36.845 ; U6.7@15.348,21.748 ccw(c15.223,21.623) 15.223,21.8 ccw(c15.223,21.977) U6.7@15.348,21.852 ; J6.7@15.35,37.29 13.675,35.615 13.675,28.575 11.4,26.3 11.4,22.825 12.425,21.8 U6.7@15.925,21.8 17.425,21.8 v1(17.45,21.775) ; U6.7@16.502,21.748 cw(c16.627,21.623) 16.627,21.8 cw(c16.627,21.977) U6.7@16.502,21.852 ; 17.022,21.8 cw(c17.022,21.347) v1@17.342,21.667 ; 17.142,21.8 ccw(c17.142,22.083) v1@17.342,21.883 ; v1@17.45,19.823 cw(c17.45,19.455) 17.71,19.715 cw(c17.97,19.975) v1@17.602,19.975 ; v1(17.45,19.975) 18.8,18.625 24.289,18.625 28.863,23.199 R25.2@28.863,27.725 ; R25.2@28.617,27.454 cw(c28.022,26.859) 28.863,26.859 cw(c29.704,26.859) R25.2@29.109,27.454
  Bottom Layer w0.203: J6.7@15.35,37.29 18.115,37.29 21.925,41.1 24.675,41.1 25.008,40.767 30.226,40.767 ; J6.7@15.815,36.975 cw(c16.575,36.215) 16.575,37.29 cw(c16.575,38.365) J6.7@15.815,37.605 ; J6.7@15.958,36.832 cw(c17.065,35.725) 17.065,37.29 cw(c17.065,38.855) J6.7@15.958,37.748 ; v1@17.342,20.083 ccw(c17.082,20.343) 17.45,20.343 ccw(c17.818,20.343) v1@17.558,20.083 ; v1@17.342,21.667 cw(c17.082,21.407) 17.45,21.407 cw(c17.818,21.407) v1@17.558,21.667 ; v1(17.45,19.975) v1(17.45,21.775) ; DS1.1@34.447,52.805 cw(c32.976,52.805) 34.016,51.764 cw(c35.057,50.724) DS1.1@35.057,52.195 ; DS1.1@34.651,52.805 cw(c33.669,52.805) 34.363,52.111 cw(c35.057,51.417) DS1.1@35.057,52.399 ; DS1.1@35.057,52.805 30.226,47.974 30.226,40.767 ; DS1.6@39.527,42.645 cw(c38.056,42.645) 39.096,41.604 cw(c40.137,40.564) DS1.6@40.137,42.035 ; DS1.6@39.731,42.645 cw(c38.749,42.645) 39.443,41.951 cw(c40.137,41.257) DS1.6@40.137,42.239 ; DS1.6@40.137,42.645 38.259,40.767 30.226,40.767
D: DS1.5 DS2.5 DS3.2 R16.2 | length 56.7
  Top Layer w0.203: R16.2@30.387,45.95 31.752,45.95 DS1.5@35.057,42.645 ; R16.2@30.633,45.704 cw(c31.228,45.109) 31.228,45.95 cw(c31.228,46.791) R16.2@30.633,46.196 ; DS1.5@34.447,42.645 ccw(c32.976,42.645) 34.016,43.686 ccw(c35.057,44.726) DS1.5@35.057,43.255 ; DS1.5@34.651,42.645 ccw(c33.669,42.645) 34.363,43.339 ccw(c35.057,44.033) DS1.5@35.057,43.051 ; DS2.5@43.032,42.645 44.329,43.942 48.968,43.942 50.619,45.593 58.142,45.593 DS3.2@61.19,42.545 ; DS2.5@43.032,43.051 ccw(c43.032,44.033) 43.726,43.339 ccw(c44.42,42.645) DS2.5@43.438,42.645 ; DS2.5@43.032,43.255 ccw(c43.032,44.726) 44.073,43.686 ccw(c45.113,42.645) DS2.5@43.642,42.645 ; 59.954,43.781 ccw(c61.19,45.017) DS3.2@61.19,43.269 ; 60.108,43.627 cw(c59.089,42.608) DS3.2@60.53,42.608 ; 60.301,43.434 ccw(c61.19,44.323) DS3.2@61.19,43.066 ; 60.454,43.281 cw(c59.782,42.608) DS3.2@60.733,42.608
  Bottom Layer w0.203: DS1.5@35.057,42.645 36.803,42.645 38.1,43.942 41.735,43.942 DS2.5@43.032,42.645 ; DS1.5@35.344,42.358 cw(c36.038,41.664) 36.038,42.645 cw(c36.038,43.626) DS1.5@35.344,42.932 ; DS1.5@35.488,42.214 cw(c36.529,41.173) 36.529,42.645 cw(c36.529,44.117) DS1.5@35.488,43.076 ; DS2.5@42.422,42.645 ccw(c40.951,42.645) 41.991,43.686 ccw(c43.032,44.726) DS2.5@43.032,43.255 ; DS2.5@42.626,42.645 ccw(c41.644,42.645) 42.338,43.339 ccw(c43.032,44.033) DS2.5@43.032,43.051
DP: DS1.7 DS2.7 DS3.3 R11.2 | length 62.1
  Top Layer w0.203: R11.2@30.387,51.75 33.086,51.75 33.401,51.435 36.576,51.435 37.15,50.861 37.15,48.172 DS1.7@40.137,45.185 ; R11.2@30.633,51.504 cw(c31.228,50.909) 31.228,51.75 cw(c31.228,52.591) R11.2@30.633,51.996 ; DS1.7@39.527,45.185 ccw(c38.056,45.185) 39.096,46.226 ccw(c40.137,47.266) DS1.7@40.137,45.795 ; DS1.7@39.731,45.185 ccw(c38.749,45.185) 39.443,45.879 ccw(c40.137,46.573) DS1.7@40.137,45.591 ; DS2.7@48.112,45.185 49.536,46.609 59.666,46.609 DS3.3@63.73,42.545 ; DS2.7@48.112,45.591 ccw(c48.112,46.573) 48.806,45.879 ccw(c49.5,45.185) DS2.7@48.518,45.185 ; DS2.7@48.112,45.795 ccw(c48.112,47.266) 49.153,46.226 ccw(c50.193,45.185) DS2.7@48.722,45.185 ; 62.494,43.781 ccw(c63.73,45.017) DS3.3@63.73,43.269 ; 62.648,43.627 cw(c61.629,42.608) DS3.3@63.07,42.608 ; 62.841,43.434 ccw(c63.73,44.323) DS3.3@63.73,43.066 ; 62.994,43.281 cw(c62.322,42.608) DS3.3@63.273,42.608
  Bottom Layer w0.203: DS1.7@40.137,45.185 41.307,46.355 41.777,46.355 ; DS1.7@40.137,45.591 ccw(c40.137,46.573) 40.831,45.879 ccw(c41.525,45.185) DS1.7@40.543,45.185 ; DS1.7@40.137,45.795 ccw(c40.137,47.266) 41.178,46.226 ccw(c42.218,45.185) DS1.7@40.747,45.185 ; 41.507,46.355 41.777,46.355 ; DS2.7@47.502,45.185 ccw(c46.031,45.185) 47.071,46.226 ccw(c48.112,47.266) DS2.7@48.112,45.795 ; DS2.7@47.706,45.185 ccw(c46.724,45.185) 47.418,45.879 ccw(c48.112,46.573) DS2.7@48.112,45.591 ; DS2.7@48.112,45.185 46.942,46.355 41.777,46.355
E: DS1.4 DS2.4 DS3.1 R15.2 | length 54.4
  Top Layer w0.203: R15.2@30.387,47.4 32.842,47.4 DS1.4@35.057,45.185 36.3,43.942 41.789,43.942 DS2.4@43.032,45.185 ; R15.2@30.633,47.154 cw(c31.228,46.559) 31.228,47.4 cw(c31.228,48.241) R15.2@30.633,47.646 ; DS1.4@34.447,45.185 ccw(c32.976,45.185) 34.016,46.226 ccw(c35.057,47.266) DS1.4@35.057,45.795 ; DS1.4@34.651,45.185 ccw(c33.669,45.185) 34.363,45.879 ccw(c35.057,46.573) DS1.4@35.057,45.591 ; DS1.4@35.057,44.575 cw(c35.057,43.104) 36.098,44.144 cw(c37.138,45.185) DS1.4@35.667,45.185 ; DS1.4@35.057,44.779 cw(c35.057,43.797) 35.751,44.491 cw(c36.445,45.185) DS1.4@35.463,45.185 ; DS2.4@42.422,45.185 cw(c40.951,45.185) 41.991,44.144 cw(c43.032,43.104) DS2.4@43.032,44.575 ; DS2.4@42.626,45.185 cw(c41.644,45.185) 42.338,44.491 cw(c43.032,43.797) DS2.4@43.032,44.779 ; v1@44.91,43.155 cw(c44.91,42.787) 45.17,43.047 cw(c45.43,43.307) v1@45.062,43.307 ; v1(44.91,43.307) 46.815,41.402 49.476,41.402 50.619,42.545 DS3.1@58.65,42.545 ; DS3.1@58.183,42.078 ccw(c57.056,40.951) 57.056,42.545 ccw(c57.056,44.139) DS3.1@58.183,43.012 ; DS3.1@58.327,42.222 ccw(c57.546,41.441) 57.546,42.545 ccw(c57.546,43.649) DS3.1@58.327,42.868
  Bottom Layer w0.203: DS2.4@43.032,44.575 cw(c43.032,43.104) 44.073,44.144 cw(c45.113,45.185) DS2.4@43.642,45.185 ; DS2.4@43.032,44.779 cw(c43.032,43.797) 43.726,44.491 cw(c44.42,45.185) DS2.4@43.438,45.185 ; DS2.4@43.032,45.185 v1(44.91,43.307) ; v1@44.758,43.307 ccw(c44.39,43.307) 44.65,43.567 ccw(c44.91,43.827) v1@44.91,43.459
F: DS1.2 DS2.2 DS3.10 R13.2 | length 57.7
  Top Layer w0.203: R13.2@30.387,48.85 v1(32.594,48.85) ; R13.2@30.633,48.604 cw(c31.228,48.009) 31.228,48.85 cw(c31.228,49.691) R13.2@30.633,49.096 ; v1@32.486,48.742 ccw(c32.226,48.482) 32.226,48.85 ccw(c32.226,49.218) v1@32.486,48.958 ; v1(37.719,51.435) 41.862,51.435 DS2.2@43.032,50.265 44.329,51.562 49.984,51.562 51.254,50.292 61.117,50.292 DS3.10@63.73,52.905 ; v1@37.827,51.327 cw(c38.087,51.067) 38.087,51.435 cw(c38.087,51.803) v1@37.827,51.543 ; DS2.2@42.422,50.265 ccw(c40.951,50.265) 41.991,51.306 ccw(c43.032,52.346) 43.032,50.875 ccw(c43.032,52.346) 44.073,51.306 ccw(c45.113,50.265) DS2.2@43.642,50.265 ; DS2.2@42.626,50.265 ccw(c41.644,50.265) 42.338,50.959 ccw(c43.032,51.653) 43.032,50.671 ccw(c43.032,51.653) 43.726,50.959 ccw(c44.42,50.265) DS2.2@43.438,50.265 ; 62.494,51.669 cw(c63.73,50.433) DS3.10@63.73,52.181 ; 62.648,51.823 ccw(c61.629,52.841) DS3.10@63.07,52.841 ; 62.841,52.016 cw(c63.73,51.127) DS3.10@63.73,52.384 ; 62.994,52.169 ccw(c62.322,52.841) DS3.10@63.273,52.841
  Bottom Layer w0.203: v1(32.594,48.85) 34.009,50.265 ; v1@32.594,49.002 ccw(c32.594,49.37) 32.854,49.11 ccw(c33.114,48.85) v1@32.746,48.85 ; DS1.2@34.527,49.964 ccw(c34.009,49.669) 34.009,50.265 ; DS1.2@34.527,50.566 cw(c34.009,50.861) 34.009,50.265 ; DS1.2@35.344,49.978 cw(c36.038,49.284) 36.038,50.265 cw(c36.038,51.246) DS1.2@35.344,50.552 ; DS1.2@35.488,49.834 cw(c36.529,48.793) 36.529,50.265 cw(c36.529,51.737) DS1.2@35.488,50.696 ; v1@37.567,51.435 cw(c37.199,51.435) 37.459,51.175 cw(c37.719,50.915) v1@37.719,51.283 ; v1(37.719,51.435) 36.549,50.265 DS1.2@35.057,50.265 34.009,50.265
G: DS1.3 DS2.3 DS3.5 R12.2 | length 65.9
  Top Layer w0.203: R12.2@30.387,50.3 32.482,50.3 DS1.3@35.057,47.725 ; R12.2@30.633,50.054 cw(c31.228,49.459) 31.228,50.3 cw(c31.228,51.141) R12.2@30.633,50.546 ; DS1.3@34.447,47.725 ccw(c32.976,47.725) 34.016,48.766 ccw(c35.057,49.806) DS1.3@35.057,48.335 ; DS1.3@34.651,47.725 ccw(c33.669,47.725) 34.363,48.419 ccw(c35.057,49.113) DS1.3@35.057,48.131 ; v1(37.973,49.149) 41.608,49.149 DS2.3@43.032,47.725 44.623,47.725 45.793,48.895 62.46,48.895 DS3.5@68.81,42.545 ; v1@38.081,49.041 cw(c38.341,48.781) 38.341,49.149 cw(c38.341,49.517) v1@38.081,49.257 ; DS2.3@42.422,47.725 ccw(c40.951,47.725) 41.991,48.766 ccw(c43.032,49.806) DS2.3@43.032,48.335 ; DS2.3@42.626,47.725 ccw(c41.644,47.725) 42.338,48.419 ccw(c43.032,49.113) DS2.3@43.032,48.131 ; DS2.3@43.319,47.438 cw(c44.013,46.744) 44.013,47.725 cw(c44.013,48.706) DS2.3@43.319,48.012 ; DS2.3@43.463,47.294 cw(c44.504,46.253) 44.504,47.725 cw(c44.504,49.197) DS2.3@43.463,48.156 ; 67.574,43.781 ccw(c68.81,45.017) DS3.5@68.81,43.269 ; 67.728,43.627 cw(c66.709,42.608) DS3.5@68.15,42.608 ; 67.921,43.434 ccw(c68.81,44.323) DS3.5@68.81,43.066 ; 68.074,43.281 cw(c67.402,42.608) DS3.5@68.353,42.608
  Bottom Layer w0.203: DS1.3@35.057,47.725 36.549,47.725 v1(37.973,49.149) ; DS1.3@35.344,47.438 cw(c36.038,46.744) 36.038,47.725 cw(c36.038,48.706) DS1.3@35.344,48.012 ; DS1.3@35.488,47.294 cw(c36.529,46.253) 36.529,47.725 cw(c36.529,49.197) DS1.3@35.488,48.156 ; v1@37.821,49.149 cw(c37.453,49.149) 37.713,48.889 cw(c37.973,48.629) v1@37.973,48.997
GND: C2.2 C3.2 C4.2 C5.2 C6.2 C7.2 C8.2 C9.2 C10.2 C11.2 J2.5 J3.2 J4.5 J4.6 J4.7 J4.8 J4.9 J4.10 J4.11 J5.6 J6.2 LED2.2 R4.1 RP1.7 S7.1 S7.4 U1.33 U2.1 U3.1 U4.2 U5.1 U5.13 U5.17 U6.2 | length 14.9
  Top Layer w0.254: 14.377,25.05 U6.2@15.925,25.05 ; C5.2@51.535,7.403 ccw(c50.983,7.955) 51.763,7.955 ccw(c52.543,7.955) C5.2@51.991,7.403 ; C6.2@51.535,8.335 cw(c50.983,7.783) 51.763,7.783 cw(c52.543,7.783) C6.2@51.991,8.335 ; C5.2@51.763,7.15 C6.2@51.763,8.588 ; U5.17@64.025,4.898 cw(c64.025,4.591) 64.242,4.808 cw(c64.459,5.025) 64.152,5.025 cw(c64.459,5.025) 64.242,5.242 cw(c64.025,5.459) U5.17@64.025,5.152 ; 64.775,7.475 U5.1@64.775,6.475 64.775,6.019 64.72,5.964 64.72,5.72 64.269,5.269 64.025,5.269 v1(64.025,5.025) 64.72,4.33 64.976,4.33 65.031,4.275 U5.13@65.475,4.275 ; 64.72,6.047 cw(c64.903,6.047) 64.774,6.176 ccw(c64.903,6.047) 64.72,6.047 ; 65.047,4.33 cw(c65.047,4.147) 65.176,4.276 ccw(c65.047,4.147) 65.047,4.33
  Top Layer w0.4: 77.475,1.125 J4.5@77.475,2.215 77.475,3.475
  Top Layer w0.508: v1(18.188,6.244) RP1.7@19.087,6.244
  other v1: 4.5,-0.5 9.5,-0.5 19.5,-0.5 34.5,-0.5 39.5,-0.5 44.5,-0.5 49.5,-0.5 57,-0.5 64.5,-0.5 69.5,-0.5 22,1.5 54.775,1.575 61.262,2.105 30,2.5 37.5,2.5 42,3 62.278,3.604 12.875,4.01 -0.5,4.5 84.5,4.5 77.5,5 70.5,5.5 31.625,5.875 51.5,6 12.773,6.271 60.5,6.5 78.825,6.625 38.5,7 42,7 56.6,7.275 65.5,7.425 27,7.5 28.5,7.5 68,7.5 12.85,7.846 23.25,7.9 35.862,8.1 50.35,8.375 27,8.5 28.5,8.5 73.5,8.5 -0.5,9.5 79.5,9.5 84.5,9.5 20,10 21.5,10.25 18,10.5 30.553,10.513 16.5,11 25.5,12 23,12.5 37.5,12.5 44,12.5 50.5,12.5 57,12.5 64,12.5 70.5,12.5 77,12.5 27,13 -0.5,14.5 13.408,14.602 84.376,15.796 32.5,16 37.5,16 44,16 50.5,16 57,16 64,16 70.5,16 77,16 2.842,16.558 20,17.5 24,17.5 28.5,18 13,18.5 17,18.5 8.5,19 -0.5,19.5 37.5,19.5 44,19.5 50.5,19.5 57,19.5 64,19.5 70.5,19.5 77,19.5 84.5,19.5 32.5,21.5 77,21.5 29.639,21.511 37.5,22 44,22 50.5,22 57,22 64,22 70.5,22 -0.5,24.5 81,25.25 14.5,25.5 44,25.5 50.5,25.5 57,25.5 64,25.5 70.5,25.5 77,25.5 3,26 7,26 37.5,26 29.639,26.591 32.052,26.591 13.5,27 15,27 3,28.5 7,28.5 10,28.5 -0.5,29.5 44,29.5 50.5,29.5 57,29.5 64,29.5 70.5,29.5 77,29.5 84.5,29.5 37.5,30 3,31 7,31 10,31 3,33.5 7,33.5 10,33.5 -0.5,34.5 84.5,34.5 3,36.5 7,36.5 10,36.5 37.5,36.5 44,36.5 50.5,36.5 57,36.5 64,36.5 70.5,36.5 77,36.5 26.8,38.45 13,38.5 -0.5,39.5 53,40.4 67.275,40.45 45.975,40.475 60.65,40.5 41.775,40.675 13,41 13,43.5 73.2,44 80.5,44 -0.5,44.5 84.5,44.5 44.975,44.825 19.5,45.5 13,46 6.575,46.125 73.2,47.5 80.5,47.5 38.7,47.65 6.5,48 19.5,48.5 64.05,48.525 -0.5,49.5 84.5,49.5 10.35,50.325 13,50.5 73.2,51 80.5,51 19.5,51.5 29.525,54.425 4.5,54.5 9.5,54.5 14.5,54.5 19.5,54.5 24.5,54.5 34.5,54.5 39.5,54.5 54.7,54.5 59.7,54.5 64.7,54.5 69.7,54.5 74.7,54.5 79.7,54.5 49.7,54.775 44.7,54.8
I2C0_SCL: J1.7 J5.2 J6.6 R9.1 U6.6 | length 103.1
  Top Layer w0.203: v1@2.348,9.95 ccw(c1.98,9.95) 2.24,10.21 ccw(c2.5,10.47) v1@2.5,10.102 ; v1(2.5,9.95) 1.969,10.481 1.969,40.55 3.134,41.715 ; J5.2@3.391,41.524 ccw(c3.134,41.447) 3.134,41.715 ; J5.2@3.391,41.906 cw(c3.134,41.983) 3.134,41.715 ; J5.2@4.457,41.895 ccw(c5.107,42.545) 5.107,41.625 ; J5.2@4.6,41.392 cw(c5.164,40.829) 5.164,41.625 ; J5.2@4.6,42.038 ccw(c5.598,43.036) 5.598,41.625 ; J5.2@4.744,41.248 cw(c5.654,40.338) 5.654,41.625 ; J5.2@4.744,42.182 ccw(c6.089,43.527) 6.089,41.625 ; R9.1@7.83,41.379 ccw(c7.235,40.784) 7.235,41.625 ccw(c7.235,42.466) R9.1@7.83,41.871 ; R9.1@8.076,41.625 4.24,41.625 J5.2@4.15,41.715 3.134,41.715 ; U6.6@15.925,22.45 17.15,22.45 18.8,24.1 v1(18.8,39.4) ; U6.6@16.502,22.398 cw(c16.627,22.273) 16.627,22.45 cw(c16.627,22.627) U6.6@16.502,22.502 ; v1@18.692,39.292 cw(c18.432,39.032) 18.8,39.032 cw(c19.168,39.032) v1@18.908,39.292
  Bottom Layer w0.203: v1@2.392,9.842 cw(c2.132,9.582) 2.5,9.582 cw(c2.868,9.582) v1@2.608,9.842 ; v1(2.5,9.95) 2.5,8.13 J1.7@4.175,6.455 ; 2.812,7.818 cw(c1.449,6.455) J1.7@3.377,6.455 ; 3.159,7.471 cw(c2.143,6.455) J1.7@3.58,6.455 ; 3.174,7.456 ccw(c4.025,8.307) J1.7@4.025,7.103 ; 3.506,7.124 cw(c2.837,6.455) J1.7@3.783,6.455 ; 3.521,7.109 ccw(c4.025,7.613) J1.7@4.025,6.9 ; J5.2@4.15,41.715 6.41,41.715 8.295,39.83 J6.6@15.35,39.83 18.37,39.83 v1(18.8,39.4) ; J5.2@4.6,41.392 cw(c5.381,40.611) 5.381,41.715 cw(c5.381,42.819) J5.2@4.6,42.038 ; J5.2@4.744,41.248 cw(c5.871,40.121) 5.871,41.715 cw(c5.871,43.309) J5.2@4.744,42.182 ; J6.6@14.742,39.372 ccw(c13.635,38.265) 13.635,39.83 ccw(c13.635,41.395) J6.6@14.742,40.288 ; J6.6@14.885,39.515 ccw(c14.125,38.755) 14.125,39.83 ccw(c14.125,40.905) J6.6@14.885,40.145 ; J6.6@15.815,39.515 cw(c16.575,38.755) 16.575,39.83 cw(c16.575,40.905) J6.6@15.815,40.145 ; J6.6@15.958,39.372 cw(c17.065,38.265) 17.065,39.83 cw(c17.065,41.395) J6.6@15.958,40.288 ; v1@18.648,39.4 ccw(c18.28,39.4) 18.54,39.66 ccw(c18.8,39.92) v1@18.8,39.552
I2C0_SDA: J1.5 J5.3 J6.5 R10.1 U6.5 | length 105.8
  Top Layer w0.203: J5.3@3.556,43.788 ccw(c2.429,42.661) 2.429,44.255 ccw(c2.429,45.849) J5.3@3.556,44.722 ; J1.5@3.567,8.537 ccw(c2.46,7.43) 2.46,8.995 ccw(c2.46,10.56) J1.5@3.567,9.453 ; J5.3@3.7,43.932 ccw(c2.919,43.151) 2.919,44.255 ccw(c2.919,45.359) J5.3@3.7,44.578 ; J1.5@3.71,8.68 ccw(c2.95,7.92) 2.95,8.995 ccw(c2.95,10.07) J1.5@3.71,9.31 ; J1.5@4.175,8.995 2.455,8.995 1.563,9.887 1.563,43.4 2.418,44.255 J5.3@4.15,44.255 5.345,43.06 R10.1@8.076,43.06 ; J5.3@4.277,43.595 cw(c4.277,42.307) 5.188,43.217 ; J5.3@4.277,43.798 cw(c4.277,43.001) 4.841,43.564 ; J5.3@4.73,44.193 ccw(c5.646,44.067) 4.992,43.413 ; J5.3@4.931,44.165 ccw(c6.155,43.997) 5.281,43.124 ; R10.1@7.83,42.814 ccw(c7.235,42.219) 7.235,43.06 ccw(c7.235,43.901) R10.1@7.83,43.306 ; U6.5@15.925,23.1 17.025,23.1 18.225,24.3 v1(18.225,41.975) ; U6.5@16.502,23.048 cw(c16.627,22.923) 16.627,23.1 cw(c16.627,23.277) U6.5@16.502,23.152 ; v1@18.117,41.867 cw(c17.857,41.607) 18.225,41.607 cw(c18.593,41.607) v1@18.333,41.867
  Bottom Layer w0.203: J5.3@4.15,44.255 5.67,44.255 ; J5.3@4.631,43.966 cw(c5.241,43.467) 5.241,44.255 cw(c5.241,45.043) J5.3@4.631,44.544 ; J5.3@4.788,43.837 cw(c5.67,43.116) 5.67,44.255 ; J5.3@4.788,44.673 ccw(c5.67,45.394) 5.67,44.255 ; J6.5@14.742,41.912 ccw(c13.635,40.805) 13.635,42.37 ccw(c13.635,43.935) J6.5@14.742,42.828 ; J6.5@14.885,42.055 ccw(c14.125,41.295) 14.125,42.37 ccw(c14.125,43.445) J6.5@14.885,42.685 ; J6.5@15.815,42.055 cw(c16.575,41.295) 16.575,42.37 cw(c16.575,43.445) J6.5@15.815,42.685 ; J6.5@15.958,41.912 cw(c17.065,40.805) 17.065,42.37 cw(c17.065,43.935) J6.5@15.958,42.828 ; v1@18.073,41.975 ccw(c17.705,41.975) 17.965,42.235 ccw(c18.225,42.495) v1@18.225,42.127 ; v1(18.225,41.975) 17.83,42.37 J6.5@15.35,42.37 7.555,42.37 5.67,44.255
ISP: J3.1 RP1.3 U1.2 | length 28.1
  Top Layer w0.203: RP1.3@20.713,7.056 21.456,7.056 v1(21.706,7.306) ; RP1.3@20.735,7.056 ccw(c20.735,8.277) v1@21.598,7.414 ; RP1.3@21.011,6.949 cw(c21.271,6.688) 21.271,7.056 cw(c21.271,7.424) RP1.3@21.011,7.164 ; 21.226,7.056 ccw(c21.226,7.786) v1@21.742,7.27 ; v1@23.975,9.423 cw(c23.975,9.055) 24.235,9.315 cw(c24.495,9.575) v1@24.127,9.575 ; v1(23.975,9.575) 24.325,9.225 U1.2@25.225,9.225
  Bottom Layer w0.203: J3.1@13.98,-0.7 13.98,-0.42 15.396,0.996 18.496,0.996 21.706,4.206 v1(21.706,7.306) v1(23.975,9.575) v1@23.975,9.475 ; J3.1@13.98,-0.105 ccw(c13.98,0.656) J3.1@14.518,0.118 ; J3.1@13.98,0.098 ccw(c13.98,1.35) 14.865,0.465 ; J3.1@14.222,-0.55 cw(c15.12,-0.55) J3.1@14.485,0.085 ; J3.1@14.425,-0.55 cw(c15.814,-0.55) 14.832,0.432 ; J3.1@14.628,-0.55 cw(c16.508,-0.55) 15.179,0.779 ; v1@21.598,7.198 cw(c21.338,6.938) 21.706,6.938 cw(c22.074,6.938) v1@21.814,7.198 ; v1@21.706,7.458 ccw(c21.706,7.826) 21.966,7.566 ccw(c22.226,7.306) v1@21.858,7.306 ; v1@23.823,9.575 cw(c23.455,9.575) 23.715,9.315 cw(c23.975,9.055) v1@23.975,9.423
